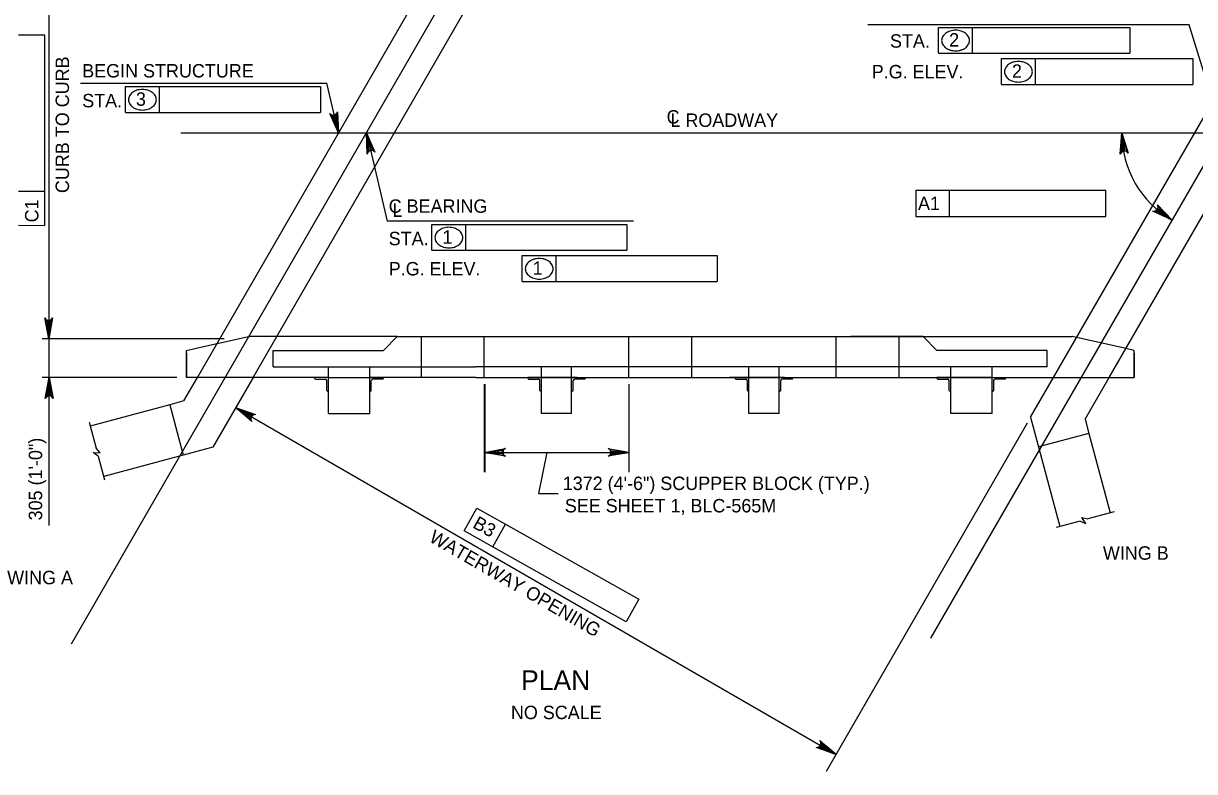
# Model space of a CAD drawing. Extents: x 638268 to 640277, y 295465 to 298435.
# Drawn here: x 638488.1 to 638750, y 298137.1 to 298304.3 of the extents above; entities that cross this region are included whole.
import ezdxf

# ---------------------------------------------------------------- set-up
doc = ezdxf.new("R2010")
doc.units = 0
for name, color, linetype in [('2', 7, 'Continuous'), ('3', 7, 'Continuous'), ('4', 7, 'Continuous')]:
    doc.layers.add(name, color=color, linetype=linetype)

msp = doc.modelspace()

# ---------------------------------------------------------------- linework, layer by layer
at = {"layer": '2'}
for p, q in [((638527.04, 298225.2), (638591.22, 298336.37)), ((638539.47, 298225.2), (638603.66, 298336.37)), ((638718.45, 298225.2), (638782.63, 298336.37)), ((638730.88, 298225.2), (638795.06, 298336.37)), ((638526.74, 298231.71), (638538.42, 298234.32)), ((638571.72, 298234.32), (638538.42, 298234.32)), ((638571.72, 298234.32), (638568.63, 298231.23)), ((638571.72, 298234.32), (638587.88, 298234.32)), ((638571.72, 298234.32), (638722.58, 298234.32)), ((638577.1, 298225.2), (638577.1, 298234.32)), ((638591.17, 298225.2), (638591.17, 298234.32)), ((638623.51, 298225.2), (638623.51, 298234.32)), ((638637.53, 298225.2), (638637.53, 298234.32)), ((638669.87, 298225.2), (638669.87, 298234.32)), ((638689.28, 298234.32), (638673.12, 298234.32)), ((638683.9, 298225.2), (638683.9, 298234.32)), ((638689.28, 298234.32), (638692.37, 298231.23)), ((638734.26, 298231.71), (638722.58, 298234.32)), ((638524.57, 298231.23), (638526.74, 298231.71)), ((638524.57, 298225.2), (638524.57, 298231.23)), ((638543.99, 298231.23), (638568.63, 298231.23)), ((638543.99, 298227.59), (638543.99, 298231.23)), ((638717.01, 298231.23), (638692.37, 298231.23)), ((638717.01, 298227.59), (638717.01, 298231.23)), ((638736.43, 298231.23), (638734.26, 298231.71)), ((638736.43, 298225.2), (638736.43, 298231.23)), ((638524.57, 298230.58), (638524.57, 298225.2)), ((638736.43, 298230.58), (638736.43, 298225.2)), ((638736.45, 298230.58), (638736.45, 298225.2)), ((638543.99, 298227.59), (638589.17, 298227.59)), ((638556.31, 298217.11), (638556.31, 298227.59)), ((638565.55, 298217.11), (638565.55, 298227.59)), ((638717.01, 298227.59), (638589.17, 298227.59)), ((638603.98, 298217.11), (638603.98, 298227.59)), ((638610.7, 298217.11), (638610.7, 298227.59)), ((638650.34, 298217.11), (638650.34, 298227.59)), ((638657.07, 298217.11), (638657.07, 298227.59)), ((638695.45, 298217.11), (638695.45, 298227.59)), ((638704.69, 298217.11), (638704.69, 298227.59)), ((638524.01, 298219.94), (638527.04, 298225.2)), ((638524.01, 298219.94), (638527.04, 298225.2)), ((638556.31, 298225.2), (638524.57, 298225.2)), ((638539.47, 298225.2), (638530.48, 298209.63)), ((638553.22, 298225.02), (638553.22, 298225.2)), ((638556.31, 298225.2), (638553.22, 298225.2)), ((638553.4, 298224.83), (638555.59, 298224.83)), ((638555.95, 298222.29), (638555.95, 298224.47)), ((638556.31, 298225.2), (638565.55, 298225.2)), ((638556.31, 298222.11), (638556.31, 298225.2)), ((638565.55, 298225.2), (638568.64, 298225.2)), ((638589.26, 298225.2), (638565.55, 298225.2)), ((638565.55, 298222.11), (638565.55, 298225.2)), ((638565.91, 298222.29), (638565.91, 298224.47)), ((638568.46, 298224.83), (638566.28, 298224.83)), ((638568.64, 298225.02), (638568.64, 298225.2)), ((638589.34, 298225.2), (638736.43, 298225.2)), ((638600.89, 298225.02), (638600.89, 298225.2)), ((638603.98, 298225.2), (638600.89, 298225.2)), ((638601.07, 298224.83), (638603.25, 298224.83)), ((638611.96, 298225.2), (638602.72, 298225.2)), ((638603.61, 298222.29), (638603.61, 298224.47)), ((638610.7, 298225.2), (638603.98, 298225.2)), ((638603.98, 298222.11), (638603.98, 298225.2)), ((638610.7, 298222.11), (638610.7, 298225.2)), ((638610.7, 298225.2), (638613.8, 298225.2)), ((638611.07, 298222.29), (638611.07, 298224.47)), ((638613.61, 298224.83), (638611.43, 298224.83)), ((638613.8, 298225.02), (638613.8, 298225.2)), ((638649.09, 298225.2), (638645.99, 298225.2)), ((638647.25, 298225.02), (638647.25, 298225.2)), ((638650.34, 298225.2), (638647.25, 298225.2)), ((638647.43, 298224.83), (638649.61, 298224.83)), ((638658.32, 298225.2), (638649.09, 298225.2)), ((638658.32, 298225.2), (638649.09, 298225.2)), ((638649.98, 298222.29), (638649.98, 298224.47)), ((638657.07, 298225.2), (638650.34, 298225.2)), ((638650.34, 298222.11), (638650.34, 298225.2)), ((638657.07, 298222.11), (638657.07, 298225.2)), ((638657.07, 298225.2), (638660.16, 298225.2)), ((638657.43, 298222.29), (638657.43, 298224.47)), ((638659.98, 298224.83), (638657.8, 298224.83)), ((638658.32, 298225.2), (638661.41, 298225.2)), ((638660.16, 298225.02), (638660.16, 298225.2)), ((638692.36, 298225.02), (638692.36, 298225.2)), ((638695.45, 298225.2), (638692.36, 298225.2)), ((638692.54, 298224.83), (638694.72, 298224.83)), ((638695.09, 298222.29), (638695.09, 298224.47)), ((638704.69, 298225.2), (638695.45, 298225.2)), ((638695.45, 298222.11), (638695.45, 298225.2)), ((638704.69, 298222.11), (638704.69, 298225.2)), ((638704.69, 298225.2), (638707.78, 298225.2)), ((638705.05, 298222.29), (638705.05, 298224.47)), ((638707.6, 298224.83), (638705.41, 298224.83)), ((638707.78, 298225.02), (638707.78, 298225.2)), ((638713.31, 298216.3), (638718.45, 298225.2)), ((638725.48, 298215.85), (638730.88, 298225.2)), ((638556.13, 298222.11), (638556.31, 298222.11)), ((638565.73, 298222.11), (638565.55, 298222.11)), ((638603.8, 298222.11), (638603.98, 298222.11)), ((638610.89, 298222.11), (638610.7, 298222.11)), ((638650.16, 298222.11), (638650.34, 298222.11)), ((638657.25, 298222.11), (638657.07, 298222.11)), ((638695.27, 298222.11), (638695.45, 298222.11)), ((638704.87, 298222.11), (638704.69, 298222.11)), ((638520.85, 298219.1), (638503.06, 298214.33)), ((638524.01, 298219.94), (638520.85, 298219.1)), ((638524.01, 298219.94), (638520.85, 298219.1)), ((638520.85, 298219.1), (638523.87, 298207.86)), ((638556.31, 298217.11), (638565.55, 298217.11)), ((638610.7, 298217.11), (638603.98, 298217.11)), ((638610.7, 298217.11), (638603.98, 298217.11)), ((638657.07, 298217.11), (638650.34, 298217.11)), ((638657.07, 298217.11), (638650.34, 298217.11)), ((638657.07, 298217.11), (638650.34, 298217.11)), ((638704.69, 298217.11), (638695.45, 298217.11)), ((638713.31, 298216.3), (638719.85, 298191.89)), ((638725.48, 298215.85), (638726.32, 298212.7)), ((638726.32, 298212.7), (638715.08, 298209.68)), ((638726.32, 298212.7), (638731.09, 298194.91)), ((638530.48, 298209.63), (638506.08, 298203.09))]:
    msp.add_line(p, q, dxfattribs=at)
for centre, radius, start, end in [((638553.4, 298225.02), 0.182, 180.0016, 270), ((638555.59, 298224.47), 0.364, 0.0016, 90), ((638566.28, 298224.47), 0.364, 90, 179.9984), ((638568.46, 298225.02), 0.182, 270, 359.9984), ((638601.07, 298225.02), 0.182, 180.0016, 270), ((638603.25, 298224.47), 0.364, 0.0016, 90), ((638611.43, 298224.47), 0.364, 90, 179.9984), ((638613.61, 298225.02), 0.182, 270, 359.9984), ((638647.43, 298225.02), 0.182, 180.0016, 270), ((638649.61, 298224.47), 0.364, 0.0016, 90), ((638657.8, 298224.47), 0.364, 90, 179.9984), ((638659.98, 298225.02), 0.182, 270, 359.9984), ((638692.54, 298225.02), 0.182, 180.0016, 270), ((638694.72, 298224.47), 0.364, 0.0016, 90), ((638705.41, 298224.47), 0.364, 90, 179.9984), ((638707.6, 298225.02), 0.182, 270, 359.9984), ((638556.13, 298222.29), 0.182, 180.0016, 270), ((638565.73, 298222.29), 0.182, 270, 359.9984), ((638603.8, 298222.29), 0.182, 180.0016, 270), ((638610.89, 298222.29), 0.182, 270, 359.9984), ((638650.16, 298222.29), 0.182, 180.0016, 270), ((638657.25, 298222.29), 0.182, 270, 359.9984), ((638695.27, 298222.29), 0.182, 180.0016, 270), ((638704.87, 298222.29), 0.182, 270, 359.9984)]:
    msp.add_arc(centre, radius, start, end, dxfattribs=at)
at = {"layer": '3'}
for p, q in [((638498.88, 298165.66), (638630.71, 298394)), ((638691.03, 298166.95), (638822.86, 298395.29)), ((638502.83, 298215.2), (638504.39, 298209.37)), ((638504.86, 298207.63), (638503.76, 298208.45)), ((638503.76, 298208.45), (638505.32, 298208.36)), ((638505.32, 298208.36), (638504.39, 298209.37)), ((638504.86, 298207.63), (638506.29, 298202.29)), ((638731.96, 298195.14), (638726.13, 298193.58)), ((638724.39, 298193.11), (638719.05, 298191.68)), ((638724.39, 298193.11), (638725.65, 298192.57)), ((638725.65, 298192.57), (638724.79, 298193.87)), ((638724.79, 298193.87), (638726.13, 298193.58))]:
    msp.add_line(p, q, dxfattribs=at)
at = {"layer": '4'}
for p, q in [((638493.78, 298373.54), (638493.78, 298192.11)), ((638492.94, 298301.69), (638487.04, 298301.7)), ((638492.94, 298259.17), (638492.94, 298301.69)), ((638748.74, 298304.01), (638676.93, 298304.01)), ((638692.75, 298303.39), (638700.33, 298303.39)), ((638692.75, 298297.62), (638692.75, 298303.39)), ((638700.33, 298297.62), (638700.33, 298303.39)), ((638700.33, 298303.39), (638735.51, 298303.39)), ((638735.51, 298303.39), (638735.51, 298297.62)), ((638756.2, 298279.83), (638748.74, 298304.01)), ((638692.75, 298297.62), (638735.51, 298297.62)), ((638706.8, 298296.42), (638714.37, 298296.42)), ((638706.8, 298290.66), (638706.8, 298296.42)), ((638714.37, 298290.66), (638714.37, 298296.42)), ((638714.37, 298296.42), (638749.56, 298296.42)), ((638749.56, 298296.42), (638749.56, 298290.66)), ((638500.9, 298290.93), (638555.97, 298290.93)), ((638510.95, 298284.4), (638510.95, 298290.17)), ((638510.95, 298290.17), (638518.53, 298290.17)), ((638518.53, 298284.4), (638518.53, 298290.17)), ((638518.53, 298290.17), (638554.54, 298290.17)), ((638554.54, 298290.17), (638554.54, 298284.4)), ((638558.58, 298279.83), (638555.97, 298290.93)), ((638706.8, 298290.66), (638749.56, 298290.66)), ((638510.95, 298284.4), (638554.54, 298284.4)), ((638523.29, 298279.83), (638808.3, 298279.83)), ((638564.8, 298279.83), (638569.42, 298260.13)), ((638492.94, 298266.73), (638487.04, 298266.74)), ((638687.63, 298267.05), (638687.62, 298261.14)), ((638687.63, 298267.05), (638695.19, 298267.05)), ((638695.19, 298261.14), (638695.19, 298267.05)), ((638695.19, 298267.05), (638730.15, 298267.05)), ((638730.14, 298261.14), (638730.15, 298267.05)), ((638624.5, 298260.13), (638569.42, 298260.13)), ((638687.62, 298261.14), (638730.14, 298261.14)), ((638487.04, 298259.18), (638492.94, 298259.17)), ((638579.47, 298259.36), (638587.05, 298259.36)), ((638579.47, 298253.6), (638579.47, 298259.36)), ((638587.05, 298253.6), (638587.05, 298259.36)), ((638587.05, 298259.36), (638623.06, 298259.36)), ((638623.06, 298259.36), (638623.06, 298253.6)), ((638579.47, 298253.6), (638623.06, 298253.6)), ((638599.66, 298246.63), (638599.66, 298252.4)), ((638599.66, 298252.4), (638607.24, 298252.4)), ((638607.24, 298246.63), (638607.24, 298252.4)), ((638607.24, 298252.4), (638643.25, 298252.4)), ((638643.25, 298252.4), (638643.25, 298246.63)), ((638599.66, 298246.63), (638643.25, 298246.63)), ((638533.01, 298233.85), (638492.34, 298233.85)), ((638522.43, 298225.2), (638492.34, 298225.2)), ((638591.17, 298223.66), (638591.17, 298204.02)), ((638591.27, 298223.66), (638591.27, 298204.02)), ((638623.51, 298223.66), (638623.51, 298204.02)), ((638535.58, 298218.46), (638669.81, 298140.96)), ((638712.54, 298214.97), (638667.6, 298137.13)), ((638591.17, 298208.45), (638623.51, 298208.45)), ((638591.27, 298208.45), (638618.98, 298208.45)), ((638605.12, 298208.45), (638603.28, 298199.23)), ((638605.12, 298208.45), (638603.28, 298199.23)), ((638603.28, 298199.23), (638607.71, 298199.23)), ((638603.28, 298199.23), (638607.71, 298199.23)), ((638586.68, 298190.95), (638589.51, 298195.97)), ((638589.51, 298195.97), (638595.91, 298192.37)), ((638593.09, 298187.35), (638595.91, 298192.37)), ((638595.91, 298192.37), (638625.7, 298175.63)), ((638622.88, 298170.6), (638586.68, 298190.95)), ((638625.7, 298175.63), (638622.88, 298170.6))]:
    msp.add_line(p, q, dxfattribs=at)
for points in [[(638558.58, 298279.83), (638556.66, 298284.17), (638556.99, 298283.87), (638557.34, 298283.77), (638557.65, 298283.78), (638557.94, 298283.91), (638558.21, 298284.16), (638558.37, 298284.57), (638558.58, 298279.83), (638558.21, 298284.16), (638557.94, 298283.91), (638558.58, 298279.83), (638557.65, 298283.78), (638557.34, 298283.77), (638558.58, 298279.83), (638556.99, 298283.87)], [(638564.8, 298279.83), (638566.71, 298275.49), (638566.39, 298275.79), (638566.04, 298275.9), (638565.72, 298275.88), (638565.43, 298275.75), (638565.17, 298275.5), (638565.01, 298275.09), (638564.8, 298279.83), (638565.17, 298275.5), (638565.43, 298275.75), (638564.8, 298279.83), (638565.72, 298275.88), (638566.04, 298275.9), (638564.8, 298279.83), (638566.39, 298275.79)], [(638733.67, 298279.83), (638735.1, 298275.31), (638734.81, 298275.64), (638734.48, 298275.78), (638734.16, 298275.8), (638733.86, 298275.71), (638733.57, 298275.48), (638733.36, 298275.1), (638733.67, 298279.83), (638733.57, 298275.48), (638733.86, 298275.71), (638733.67, 298279.83), (638734.16, 298275.8), (638734.48, 298275.78), (638733.67, 298279.83), (638734.81, 298275.64)], [(638744.94, 298260.31), (638740.64, 298262.33), (638741.08, 298262.32), (638741.41, 298262.47), (638741.64, 298262.69), (638741.78, 298262.97), (638741.81, 298263.33), (638741.67, 298263.75), (638744.94, 298260.31), (638741.81, 298263.33), (638741.78, 298262.97), (638744.94, 298260.31), (638741.64, 298262.69), (638741.41, 298262.47), (638744.94, 298260.31), (638741.08, 298262.32)], [(638493.78, 298233.85), (638492.9, 298238.51), (638493.15, 298238.15), (638493.46, 298237.97), (638493.78, 298237.91), (638494.09, 298237.97), (638494.4, 298238.15), (638494.65, 298238.51), (638493.78, 298233.85), (638494.4, 298238.15), (638494.09, 298237.97), (638493.78, 298233.85), (638493.78, 298237.91), (638493.46, 298237.97), (638493.78, 298233.85), (638493.15, 298238.15)], [(638493.89, 298225.18), (638494.76, 298220.52), (638494.51, 298220.88), (638494.2, 298221.07), (638493.89, 298221.12), (638493.57, 298221.07), (638493.26, 298220.88), (638493.01, 298220.52), (638493.89, 298225.18), (638493.26, 298220.88), (638493.57, 298221.07), (638493.89, 298225.18), (638493.89, 298221.12), (638494.2, 298221.07), (638493.89, 298225.18), (638494.51, 298220.88)], [(638535.58, 298218.46), (638540.05, 298216.89), (638539.62, 298216.85), (638539.3, 298216.67), (638539.1, 298216.43), (638538.99, 298216.13), (638538.99, 298215.77), (638539.18, 298215.37), (638535.58, 298218.46), (638538.99, 298215.77), (638538.99, 298216.13), (638535.58, 298218.46), (638539.1, 298216.43), (638539.3, 298216.67), (638535.58, 298218.46), (638539.62, 298216.85)], [(638535.58, 298218.46), (638540.05, 298216.89), (638539.62, 298216.85), (638539.3, 298216.67), (638539.1, 298216.43), (638538.99, 298216.13), (638538.99, 298215.77), (638539.18, 298215.37), (638535.58, 298218.46), (638538.99, 298215.77), (638538.99, 298216.13), (638535.58, 298218.46), (638539.1, 298216.43), (638539.3, 298216.67), (638535.58, 298218.46), (638539.62, 298216.85)], [(638591.17, 298208.45), (638595.83, 298209.32), (638595.47, 298209.08), (638595.29, 298208.76), (638595.23, 298208.45), (638595.29, 298208.14), (638595.47, 298207.83), (638595.83, 298207.58), (638591.17, 298208.45), (638595.47, 298207.83), (638595.29, 298208.14), (638591.17, 298208.45), (638595.23, 298208.45), (638595.29, 298208.76), (638591.17, 298208.45), (638595.47, 298209.08)], [(638591.27, 298208.45), (638595.93, 298209.32), (638595.57, 298209.08), (638595.39, 298208.76), (638595.34, 298208.45), (638595.39, 298208.14), (638595.57, 298207.83), (638595.93, 298207.58), (638591.27, 298208.45), (638595.57, 298207.83), (638595.39, 298208.14), (638591.27, 298208.45), (638595.34, 298208.45), (638595.39, 298208.76), (638591.27, 298208.45), (638595.57, 298209.08)], [(638623.51, 298208.45), (638618.85, 298207.58), (638619.21, 298207.83), (638619.39, 298208.14), (638619.45, 298208.45), (638619.39, 298208.76), (638619.21, 298209.08), (638618.85, 298209.32), (638623.51, 298208.45), (638619.21, 298209.08), (638619.39, 298208.76), (638623.51, 298208.45), (638619.45, 298208.45), (638619.39, 298208.14), (638623.51, 298208.45), (638619.21, 298207.83)], [(638669.81, 298140.96), (638665.34, 298142.53), (638665.78, 298142.57), (638666.09, 298142.75), (638666.29, 298142.99), (638666.4, 298143.29), (638666.4, 298143.65), (638666.21, 298144.05), (638669.81, 298140.96), (638666.4, 298143.65), (638666.4, 298143.29), (638669.81, 298140.96), (638666.29, 298142.99), (638666.09, 298142.75), (638669.81, 298140.96), (638665.78, 298142.57)]]:
    msp.add_lwpolyline(points, dxfattribs=at)
for points in [[(638564.99, 298276.84), (638565.95, 298277.07), (638564.8, 298279.83)], [(638493.3, 298236.73), (638494.26, 298236.73), (638493.78, 298233.85)], [(638493.3, 298222.31), (638494.26, 298222.31), (638493.78, 298225.2)], [(638594.13, 298208.95), (638594.13, 298207.96), (638591.17, 298208.45)], [(638594.23, 298208.95), (638594.23, 298207.96), (638591.27, 298208.45)], [(638620.56, 298208.95), (638620.56, 298207.96), (638623.51, 298208.45)], [(638667.5, 298142.87), (638667.01, 298142.01), (638669.81, 298140.96)]]:
    msp.add_lwpolyline(points, close=True, dxfattribs=at)
for centre, radius, start, end in [((638695.81, 298300.08), 2.49, 126.3544, 150.6308), ((638696.25, 298299.48), 3.23, 106.9552, 126.3544), ((638696.54, 298298.54), 4.22, 90, 106.9552), ((638696.54, 298298.54), 4.22, 73.0448, 90), ((638696.83, 298299.48), 3.23, 53.6456, 73.0448), ((638697.27, 298300.08), 2.49, 29.3692, 53.6456), ((638695.13, 298300.46), 1.71, 150.6308, 180), ((638695.13, 298300.46), 1.71, 180, 209.3692), ((638695.81, 298300.84), 2.49, 209.3692, 233.6456), ((638696.25, 298301.44), 3.23, 233.6456, 253.0448), ((638696.83, 298301.44), 3.23, 286.9552, 306.3544), ((638697.27, 298300.84), 2.49, 306.3544, 330.6308), ((638697.95, 298300.46), 1.71, 0, 29.3692), ((638697.95, 298300.46), 1.71, 330.6308, 0), ((638696.54, 298302.39), 4.22, 253.0448, 270), ((638696.54, 298302.39), 4.22, 270, 286.9552), ((638709.17, 298293.49), 1.71, 150.6308, 180), ((638709.85, 298293.11), 2.49, 126.3544, 150.6308), ((638710.29, 298292.51), 3.23, 106.9552, 126.3544), ((638710.58, 298291.57), 4.22, 90, 106.9552), ((638710.58, 298291.57), 4.22, 73.0448, 90), ((638710.87, 298292.51), 3.23, 53.6456, 73.0448), ((638711.31, 298293.11), 2.49, 29.3692, 53.6456), ((638711.99, 298293.49), 1.71, 0, 29.3692), ((638709.17, 298293.49), 1.71, 180, 209.3692), ((638709.85, 298293.88), 2.49, 209.3692, 233.6456), ((638710.29, 298294.47), 3.23, 233.6456, 253.0448), ((638710.58, 298295.42), 4.22, 253.0448, 270), ((638710.58, 298295.42), 4.22, 270, 286.9552), ((638710.87, 298294.47), 3.23, 286.9552, 306.3544), ((638711.31, 298293.88), 2.49, 306.3544, 330.6308), ((638711.99, 298293.49), 1.71, 330.6308, 0), ((638514.01, 298286.86), 2.49, 126.3544, 150.6308), ((638514.45, 298286.26), 3.23, 106.9552, 126.3544), ((638514.74, 298285.31), 4.22, 90, 106.9552), ((638514.74, 298285.31), 4.22, 73.0448, 90), ((638515.02, 298286.26), 3.23, 53.6456, 73.0448), ((638515.47, 298286.86), 2.49, 29.3692, 53.6456), ((638513.33, 298287.24), 1.71, 150.6308, 180), ((638513.33, 298287.24), 1.71, 180, 209.3692), ((638514.01, 298287.62), 2.49, 209.3692, 233.6456), ((638515.47, 298287.62), 2.49, 306.3544, 330.6308), ((638516.14, 298287.24), 1.71, 0, 29.3692), ((638516.14, 298287.24), 1.71, 330.6308, 0), ((638514.45, 298288.22), 3.23, 233.6456, 253.0448), ((638514.74, 298289.16), 4.22, 253.0448, 270), ((638514.74, 298289.16), 4.22, 270, 286.9552), ((638515.02, 298288.22), 3.23, 286.9552, 306.3544), ((638756.21, 298279.83), 22.54, 179.9993, 239.9995), ((638581.85, 298256.43), 1.71, 150.6308, 180), ((638582.53, 298256.05), 2.49, 126.3544, 150.6308), ((638582.97, 298255.45), 3.23, 106.9552, 126.3544), ((638583.26, 298254.51), 4.22, 90, 106.9552), ((638583.26, 298254.51), 4.22, 73.0448, 90), ((638583.54, 298255.45), 3.23, 53.6456, 73.0448), ((638583.99, 298256.05), 2.49, 29.3692, 53.6456), ((638584.66, 298256.43), 1.71, 0, 29.3692), ((638581.85, 298256.43), 1.71, 180, 209.3692), ((638582.53, 298256.81), 2.49, 209.3692, 233.6456), ((638582.97, 298257.41), 3.23, 233.6456, 253.0448), ((638583.26, 298258.36), 4.22, 253.0448, 270), ((638583.26, 298258.36), 4.22, 270, 286.9552), ((638583.54, 298257.41), 3.23, 286.9552, 306.3544), ((638583.99, 298256.81), 2.49, 306.3544, 330.6308), ((638584.66, 298256.43), 1.71, 330.6308, 0), ((638603.45, 298247.54), 4.22, 90, 106.9552), ((638603.45, 298247.54), 4.22, 73.0448, 90), ((638602.04, 298249.47), 1.71, 150.6308, 180), ((638602.04, 298249.47), 1.71, 180, 209.3692), ((638602.72, 298249.09), 2.49, 126.3544, 150.6308), ((638603.16, 298248.49), 3.23, 106.9552, 126.3544), ((638603.73, 298248.49), 3.23, 53.6456, 73.0448), ((638604.18, 298249.09), 2.49, 29.3692, 53.6456), ((638604.85, 298249.47), 1.71, 0, 29.3692), ((638604.85, 298249.47), 1.71, 330.6308, 0), ((638602.72, 298249.85), 2.49, 209.3692, 233.6456), ((638603.16, 298250.45), 3.23, 233.6456, 253.0448), ((638603.45, 298251.39), 4.22, 253.0448, 270), ((638603.45, 298251.39), 4.22, 270, 286.9552), ((638603.73, 298250.45), 3.23, 286.9552, 306.3544), ((638604.18, 298249.85), 2.49, 306.3544, 330.6308)]:
    msp.add_arc(centre, radius, start, end, dxfattribs=at)

# ---------------------------------------------------------------- texts
for s, height, p in [('STA.', 3, (638681.87, 298298.87)), ('2', 3, (638695.09, 298299.11)), ('BEGIN STRUCTURE', 3, (638501.28, 298292.21)), ('P.G. ELEV.', 3, (638677.78, 298292.01)), ('2', 3, (638709.13, 298292.14)), ('STA.', 3, (638501.28, 298285.54)), ('3', 3, (638513.29, 298285.89)), ('C', 3, (638631.92, 298281.91)), ('L ROADWAY', 3, (638632.78, 298281.17)), ('C BEARING', 3, (638569.8, 298261.97)), ('L', 3, (638570.62, 298261.06)), ('STA.', 3, (638569.8, 298254.73)), ('1', 3, (638581.81, 298255.08)), ('P.G. ELEV.', 3, (638569.8, 298247.98)), ('1', 3, (638601.99, 298248.12)), ('1372 (4\'-6") SCUPPER BLOCK (TYP.)', 3, (638608.71, 298200.03)), ('SEE SHEET 1, BLC-565M', 3, (638609.17, 298195.03)), ('WING B', 3, (638729.47, 298184.46)), ('WING A', 3, (638484.5, 298178.98)), ('PLAN', 4.429, (638599.39, 298155.32)), ('NO SCALE', 3, (638597.12, 298148.84))]:
    msp.add_text(s, height=height, dxfattribs=at).set_placement(p)
for s, rotation, p in [('CURB TO CURB', 90, (638498.33, 298266.38)), ('A1', 359.9382, (638688.14, 298262.6)), ('C1', 89.9382, (638491.49, 298259.83)), ('305 (1\'-0")', 90, (638492.32, 298193.25)), ('B3', 330.6611, (638588.36, 298191.75)), ('WATERWAY OPENING', 330, (638578.61, 298188.68))]:
    msp.add_text(s, height=3, rotation=rotation, dxfattribs=at).set_placement(p)

doc.saveas('drawing.dxf')
